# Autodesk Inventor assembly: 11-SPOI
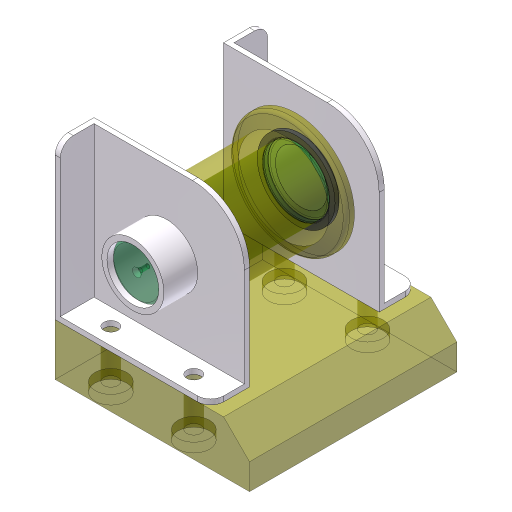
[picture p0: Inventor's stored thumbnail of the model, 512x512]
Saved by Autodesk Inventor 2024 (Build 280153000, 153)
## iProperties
Company: ATC
Created: 2023-03
Part Number: 11-SPOI
Document SubType Name: Assembly
Designer: Andrzej Jaskulski
Mass: 1986.93 g
Surface Area: 612.19 cm^2
Volume: 198.693 cm^3
Density: 10 g/cm^3
Checked By: A.J.
Engr Approved By: Andrzej Jaskulski
Mfg Approved By: Andrzej Jaskulski
Authority: A.J.
Title: A.J.: Kurs R2024-MEP
Author: Andrzej Jaskulski
Revision Number: 1/24
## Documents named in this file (4)
- C:\Users\AndJas\Documents\R2024-MEP\Obszar roboczy\11-SPOI.iam
- C:\Users\AndJas\Documents\R2024-MEP\Obszar roboczy\SPOI-Podstawa.ipt
- C:\Users\AndJas\Documents\R2024-MEP\Obszar roboczy\SPOI-Podpora.ipt
- C:\Users\AndJas\Documents\R2024-MEP\Obszar roboczy\SPOI-Zespół rolki.iam
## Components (4 placed, 3 different names)
1. SPOI-Podstawa:1 — Zestawiający:1, Zestawiający:2, Zestawiający:3, Zestawiający:4
2. SPOI-Podpora:1 — Zestawiający:1, Zestawiający:3, Wstaw:1
3. SPOI-Podpora:2 — Zestawiający:2, Zestawiający:4
4. SPOI-Zespół rolki:1 [sub-assembly] — Wstaw:1
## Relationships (5: Mate 4, Insert 1)
- Zestawiający:1 [Mate]: SPOI-Podstawa:1 ↔ SPOI-Podpora:1
- Zestawiający:2 [Mate]: SPOI-Podstawa:1 ↔ SPOI-Podpora:2
- Zestawiający:3 [Mate]: SPOI-Podstawa:1 ↔ SPOI-Podpora:1
- Zestawiający:4 [Mate]: SPOI-Podstawa:1 ↔ SPOI-Podpora:2
- Wstaw:1 [Insert]: SPOI-Podpora:1 ↔ SPOI-Zespół rolki:1
